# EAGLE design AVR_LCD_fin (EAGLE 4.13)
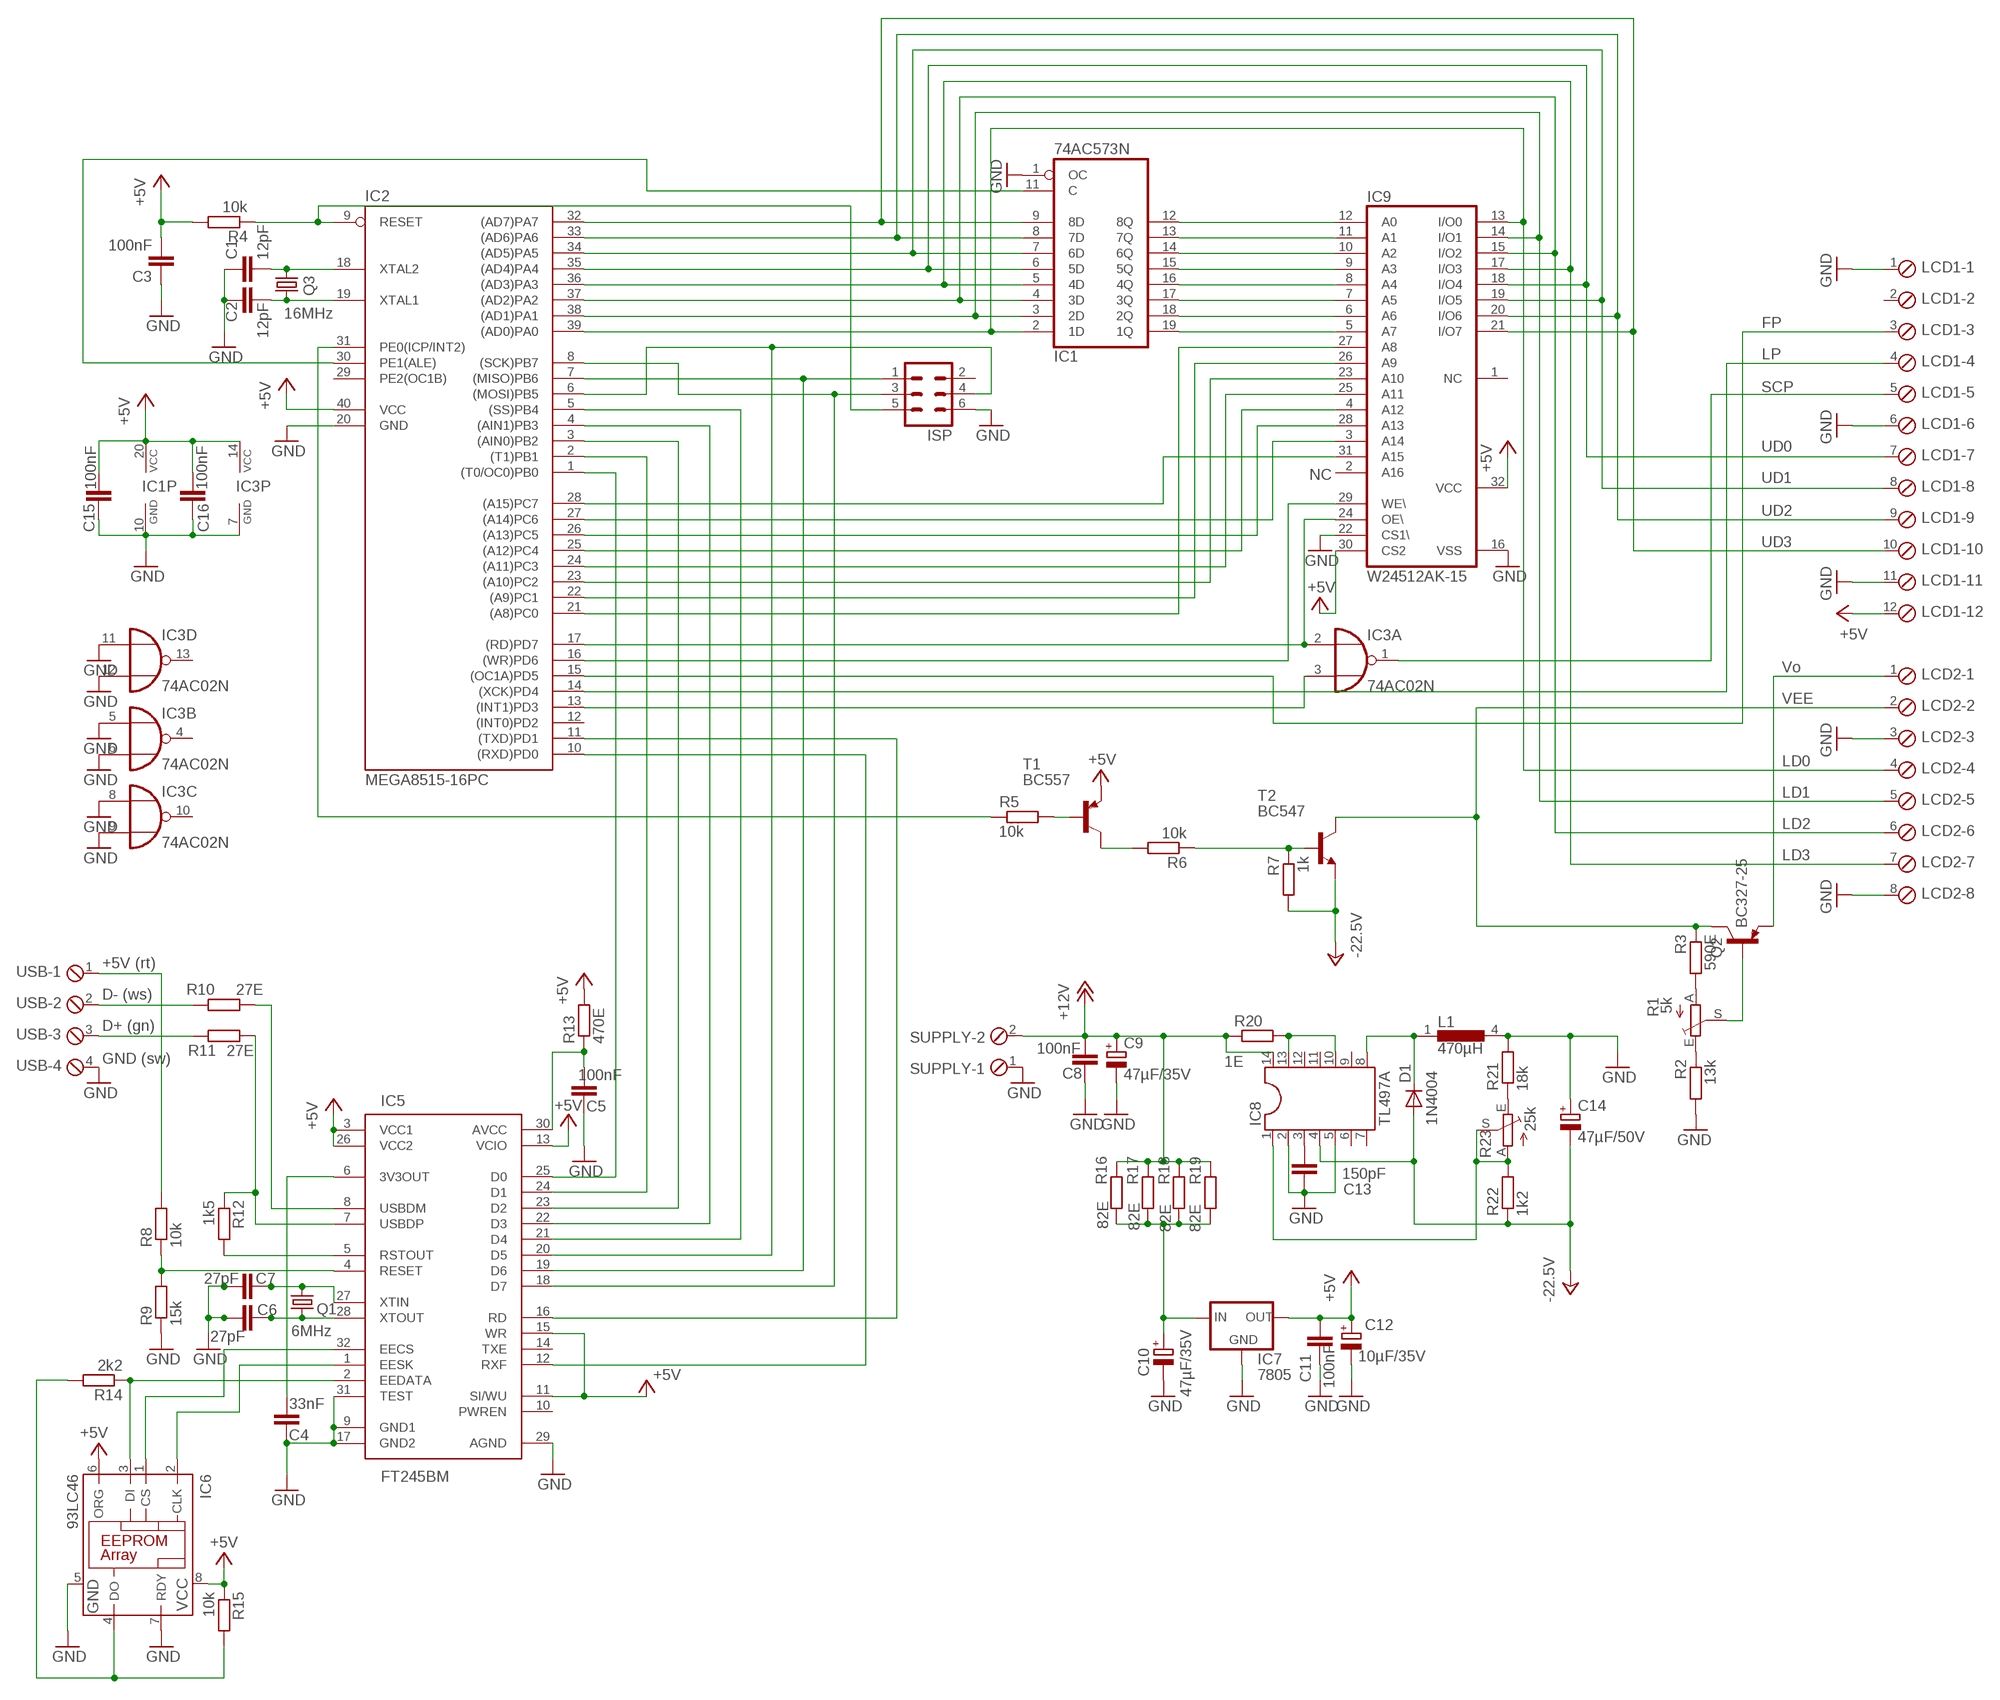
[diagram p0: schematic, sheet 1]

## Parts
C1  12pF  C-EU025-025X050  [C025-025X050]
C2  12pF  C-EU025-025X050  [C025-025X050]
C3  100nF  C-EU025-025X050  [C025-025X050]
C4  33nF  C-EU025-025X050  [C025-025X050]
C5  100nF  C-EU025-025X050  [C025-025X050]
C6  27pF  C-EU025-025X050  [C025-025X050]
C7  27pF  C-EU025-025X050  [C025-025X050]
C8  100nF  C-EU025-025X050  [C025-025X050]
C9  47µF/35V  CPOL-EUE2,5-6E  [E2,5-6E]
C10  47µF/35V  CPOL-EUE2,5-6E  [E2,5-6E]
C11  100nF  C-EU025-025X050  [C025-025X050]
C12  10µF/35V  CPOL-EUE2,5-6E  [E2,5-6E]
C13  150pF  C-EU025-025X050  [C025-025X050]
C14  47µF/50V  CPOL-EUE2,5-6E  [E2,5-6E]
C15  100nF  C-EU025-025X050  [C025-025X050]
C16  100nF  C-EU025-025X050  [C025-025X050]
D1  1N4004  [DO41-10]
IC1  74AC573N  [DIL20]
IC2  MEGA8515-16PC  MEGA8515-P  [DIL40]
IC3  74AC02N  [DIL14]
IC5  FT245BM  [QFP-32]
IC6  93LC46  59C11P  [DIL8]
IC7  7805  78XXL  [78XXL]
IC8  TL497A  DIL14S  [SOCKED-14]
IC9  W24512AK-15  628128PDIL32-3  [DIL32-3]
ISP  ML6  [ML6]
L1  470µH  SPULE  [DSH02]
LCD1  MPT12  [12POL254]
LCD2  MPT8  [8POL254]
Q1  6MHz  CRYTALHC49U70  [HC49U70]
Q2  BC327-25  [TO92-EBC]
Q3  16MHz  CRYTALHC49U-V  [HC49U-V]
R1  5k  TRIM_EU-LI10  [LI10]
R2  13k  R-EU_0207/7  [0207/7]
R3  590E  R-EU_0207/7  [0207/7]
R4  10k  R-EU_0207/7  [0207/7]
R5  10k  R-EU_0207/7  [0207/7]
R6  10k  R-EU_0207/7  [0207/7]
R7  1k  R-EU_0207/7  [0207/7]
R8  10k  R-EU_0207/7  [0207/7]
R9  15k  R-EU_0207/7  [0207/7]
R10  27E  R-EU_0207/7  [0207/7]
R11  27E  R-EU_0207/7  [0207/7]
R12  1k5  R-EU_0207/7  [0207/7]
R13  470E  R-EU_0207/7  [0207/7]
R14  2k2  R-EU_0207/7  [0207/7]
R15  10k  R-EU_0207/7  [0207/7]
R16  82E  R-EU_0207/7  [0207/7]
R17  82E  R-EU_0207/7  [0207/7]
R18  82E  R-EU_0207/7  [0207/7]
R19  82E  R-EU_0207/7  [0207/7]
R20  1E  R-EU_MELF0204W  [MINI_MELF-0204W]
R21  18k  R-EU_0207/7  [0207/7]
R22  1k2  R-EU_0207/7  [0207/7]
R23  25k  TRIM_EU-LI10  [LI10]
SUPPLY  MPT2  [2POL254]
T1  BC557  BC557B-PNP-TO92-EBC  [TO92-EBC]
T2  BC547  BC547B-NPN-TO92-EBC  [TO92-EBC]
USB  MPT4  [4POL254]

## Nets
+5V: C3.2 C11.2 C12.+ C15.2 C16.2 IC1.20(VCC) IC2.40(VCC) IC3.14(P:VCC) IC5.3(VCC1) IC5.11(SI/WU) IC5.13(VCIO) IC5.15(WR) IC5.26(VCC2) IC6.6(ORG) IC6.8(VCC) IC7.OUT IC9.30(CS2) IC9.32(VCC) LCD1.12 R4.2 R13.2 R15.1 T1.E
+12V: C8.2 C9.+ IC8.14 R16.2 R17.2 R18.2 R19.2 R20.1 SUPPLY.2
-24V: C14.- D1.A IC8.4 R7.2 R22.1 T2.E ; supply symbol labelled -22.5V
GND: C1.1 C2.1 C3.1 C4.1 C5.1 C6.2 C7.2 C8.1 C9.- C10.- C11.1 C12.- C13.1 C14.+ C15.1 C16.1 IC1.1(OC) IC1.10(GND) IC2.20(GND) IC3.5(B:I0) IC3.6(B:I1) IC3.7(P:GND) IC3.8(C:I0) IC3.9(C:I1) IC3.11(D:I0) IC3.12(D:I1) IC5.9(GND1) IC5.17(GND2) IC5.29(AGND) IC5.31(TEST) IC6.5(GND) IC6.7(RDY) IC7.GND IC8.2 IC8.5 IC9.16(VSS) IC9.22(CS1\) ISP.6 L1.4 LCD1.1 LCD1.6 LCD1.11 LCD2.3 LCD2.8 R2.2 R9.1 R21.2 SUPPLY.1 USB.4
N$1: R1.E R2.1
N$2: R1.A R3.2
N$3: IC2.9(RESET) ISP.5 R4.1
N$4: C1.2 IC2.18(XTAL2) Q3.2
N$5: C2.2 IC2.19(XTAL1) Q3.1
N$6: Q2.B R1.S
N$7: LCD2.1 Q2.E
N$8: R6.2 T1.C
N$9: R6.1 R7.1 T2.B
N$10: LCD2.2 Q2.C R3.1 T2.C
N$11: IC2.31(PE0(ICP/INT2)) R5.1
N$12: R5.2 T1.B
N$13: IC1.9(8D) IC2.32((AD7)PA7) IC9.21(I/O7) LCD1.10
N$14: IC1.8(7D) IC2.33((AD6)PA6) IC9.20(I/O6) LCD1.9
N$15: IC1.7(6D) IC2.34((AD5)PA5) IC9.19(I/O5) LCD1.8
N$16: IC1.6(5D) IC2.35((AD4)PA4) IC9.18(I/O4) LCD1.7
N$17: IC1.5(4D) IC2.36((AD3)PA3) IC9.17(I/O3) LCD2.7
N$18: IC1.4(3D) IC2.37((AD2)PA2) IC9.15(I/O2) LCD2.6
N$19: IC2.7((MISO)PB6) IC5.19(D6) ISP.1
N$20: IC2.8((SCK)PB7) IC5.18(D7) ISP.3
N$21: IC2.6((MOSI)PB5) IC5.20(D5) ISP.4
N$22: IC1.3(2D) IC2.38((AD1)PA1) IC9.14(I/O1) LCD2.5
N$23: IC1.2(1D) IC2.39((AD0)PA0) IC9.13(I/O0) LCD2.4
N$24: IC1.12(8Q) IC9.12(A0)
N$25: IC1.13(7Q) IC9.11(A1)
N$26: IC1.14(6Q) IC9.10(A2)
N$27: IC1.15(5Q) IC9.9(A3)
N$28: IC1.16(4Q) IC9.8(A4)
N$29: IC1.17(3Q) IC9.7(A5)
N$30: IC1.18(2Q) IC9.6(A6)
N$31: IC1.19(1Q) IC9.5(A7)
N$32: IC2.17((RD)PD7) IC3.2(A:I0) IC9.24(OE\)
N$33: IC2.16((WR)PD6) IC9.29(WE\)
N$34: IC2.13((INT1)PD3) IC3.3(A:I1)
N$35: IC3.1(A:O) LCD1.5
N$36: IC2.15((OC1A)PD5) LCD1.3
N$37: IC2.14((XCK)PD4) LCD1.4
N$38: IC1.11(C) IC2.30(PE1(ALE))
N$39: IC2.21((A8)PC0) IC9.27(A8)
N$40: IC2.22((A9)PC1) IC9.26(A9)
N$41: IC2.23((A10)PC2) IC9.23(A10)
N$42: IC2.24((A11)PC3) IC9.25(A11)
N$43: IC2.25((A12)PC4) IC9.4(A12)
N$44: IC2.26((A13)PC5) IC9.28(A13)
N$45: IC2.27((A14)PC6) IC9.3(A14)
N$46: IC2.1((T0/OC0)PB0) IC5.25(D0)
N$47: IC2.2((T1)PB1) IC5.24(D1)
N$48: IC2.3((AIN0)PB2) IC5.23(D2)
N$49: IC2.4((AIN1)PB3) IC5.22(D3)
N$50: IC2.5((SS)PB4) IC5.21(D4)
N$51: IC2.10((RXD)PD0) IC5.12(RXF)
N$53: IC5.4(RESET) R8.1 R9.2
N$54: R8.2 USB.1
N$55: R10.2 USB.2
N$56: R11.2 USB.3
N$57: IC5.7(USBDP) R11.1 R12.1
N$58: IC5.8(USBDM) R10.1
N$59: IC5.5(RSTOUT) R12.2
N$60: C4.2 IC5.6(3V3OUT)
N$61: C5.2 IC5.30(AVCC) R13.1
N$62: IC5.2(EEDATA) IC6.3(DI) R14.1
N$63: IC6.4(DO) R14.2 R15.2
N$64: IC5.32(EECS) IC6.1(CS)
N$65: IC5.1(EESK) IC6.2(CLK)
N$67: C6.1 IC5.28(XTOUT) Q1.1
N$68: C7.1 IC5.27(XTIN) Q1.2
N$69: C10.+ IC7.IN R16.1 R17.1 R18.1 R19.1
N$70: IC2.28((A15)PC7) IC9.31(A15)
N$71: IC8.10 IC8.13 R20.2
N$73: C13.2 IC8.3
N$75: D1.C IC8.8 L1.1
N$78: R21.1 R23.E
N$79: IC8.1 R22.2 R23.A R23.S
POWERJACK: IC2.11((TXD)PD1) IC5.16(RD)
Unconnected: IC2.12((INT0)PD2) IC2.29(PE2(OC1B)) IC3.4(B:O) IC3.10(C:O) IC3.13(D:O) IC5.10(PWREN) IC5.14(TXE) IC8.6 IC8.7 IC8.9 IC8.11 IC8.12 IC9.1(NC) IC9.2(A16) ISP.2 LCD1.2

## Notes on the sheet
- FP
- LP
- SCP
- UD0
- NC | UD1
- UD2
- UD3
- Vo
- VEE
- LD0
- LD1
- LD2
- LD3
- +5V (rt)
- D- (ws)
- D+ (gn)
- GND (sw)

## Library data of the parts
C1-C8 C11 C13 C15 C16 = rcl:C-EU: CAPACITOR, European symbol
C9 C10 C12 C14 = rcl:CPOL-EU: POLARIZED CAPACITOR, European symbol
D1 = diode:1N4004: DIODE
IC1 = 74xx-eu:74*573: 8-bit D latch BUS DRIVER
IC2 = avr:MEGA8515-P: MICROCONTROLLER 8 Kbytes FLASH 512 bytes SRAM 512 bytes EEPROM USART 8-channel 10 bit ADC
IC3 = 74xx-eu:74*02: Quad 2-input NOR gate
IC5 = FTDI:FT245BM: FT245BM USB-Fifo FTDI
IC6 = microchip:59C11: Serial EEPROM 1 K, 5.0 V, CMOS
IC7 = v-reg:78XXL: VOLTAGE REGULATOR
IC8 = ic-package:DIL14: Dual In Line
IC9 = memory-hitachi:628128P: MEMORY
ISP = con-harting-ml:ML6: HARTING
L1 = inductors:SPULE
LCD1 = con-phoenix-254:MPT12: PHOENIX CONNECTOR
LCD2 = con-phoenix-254:MPT8: PHOENIX CONNECTOR
Q1 Q3 = crystal:CRYTAL: CRYSTAL
Q2 = transistor-pnp:BC327*: PNP Transistror
R1 R23 = pot:TRIM_EU-: POTENTIOMETER
R2-R22 = rcl:R-EU_: RESISTOR, European symbol
SUPPLY = con-phoenix-254:MPT2: PHOENIX CONNECTOR
T1 = transistor:*-PNP-: PNP Transistror
T2 = transistor:*-NPN-: NPN Transistror
USB = con-phoenix-254:MPT4: PHOENIX CONNECTOR

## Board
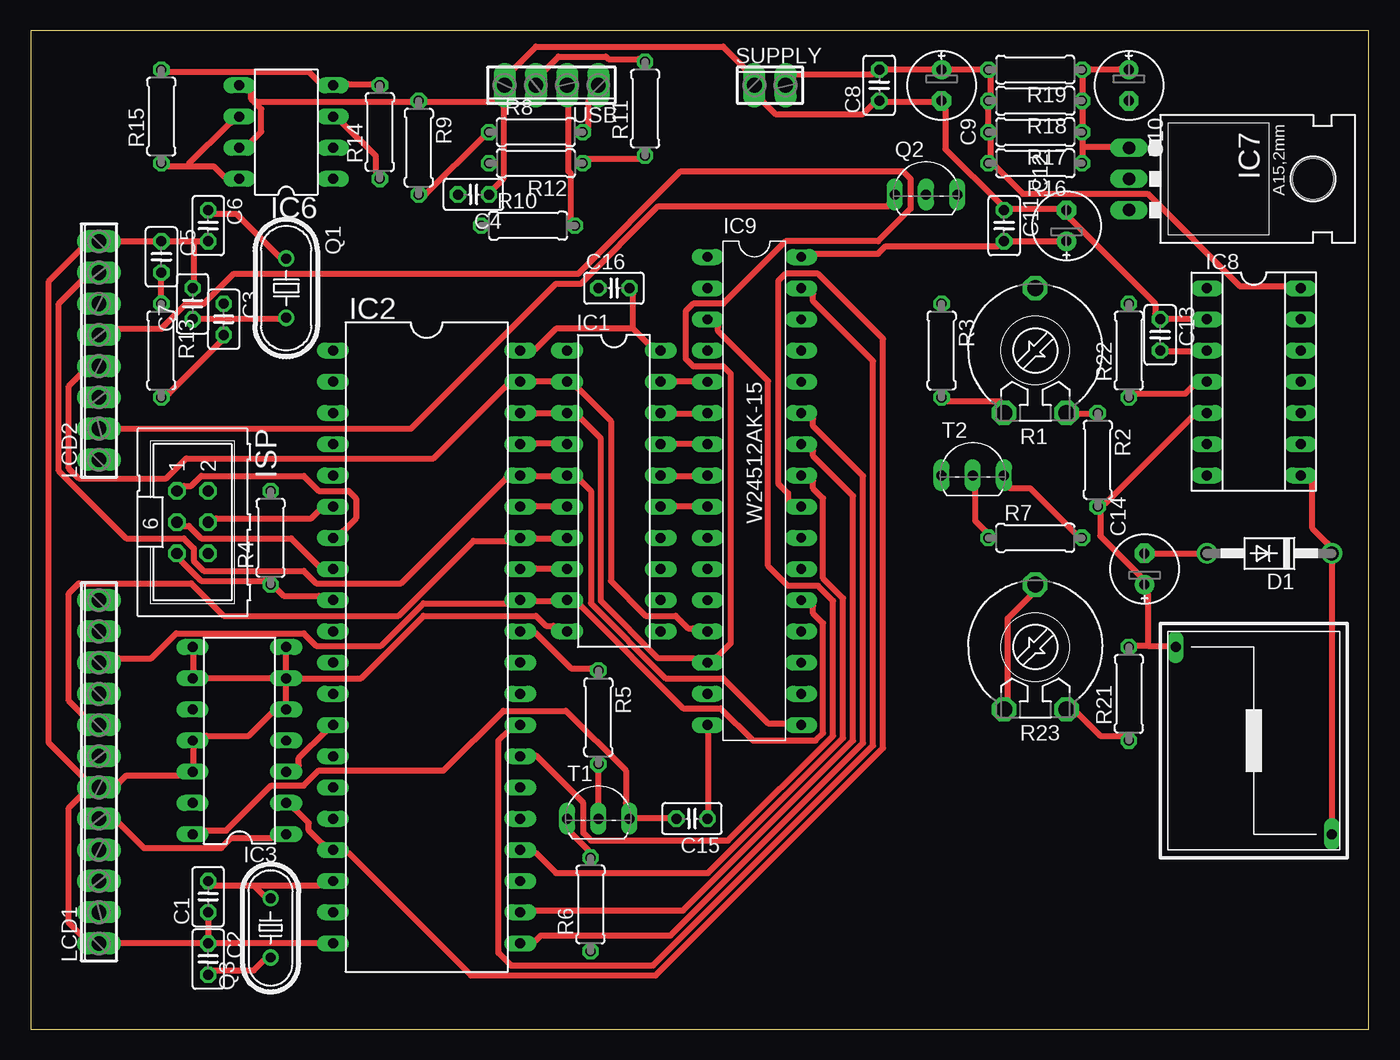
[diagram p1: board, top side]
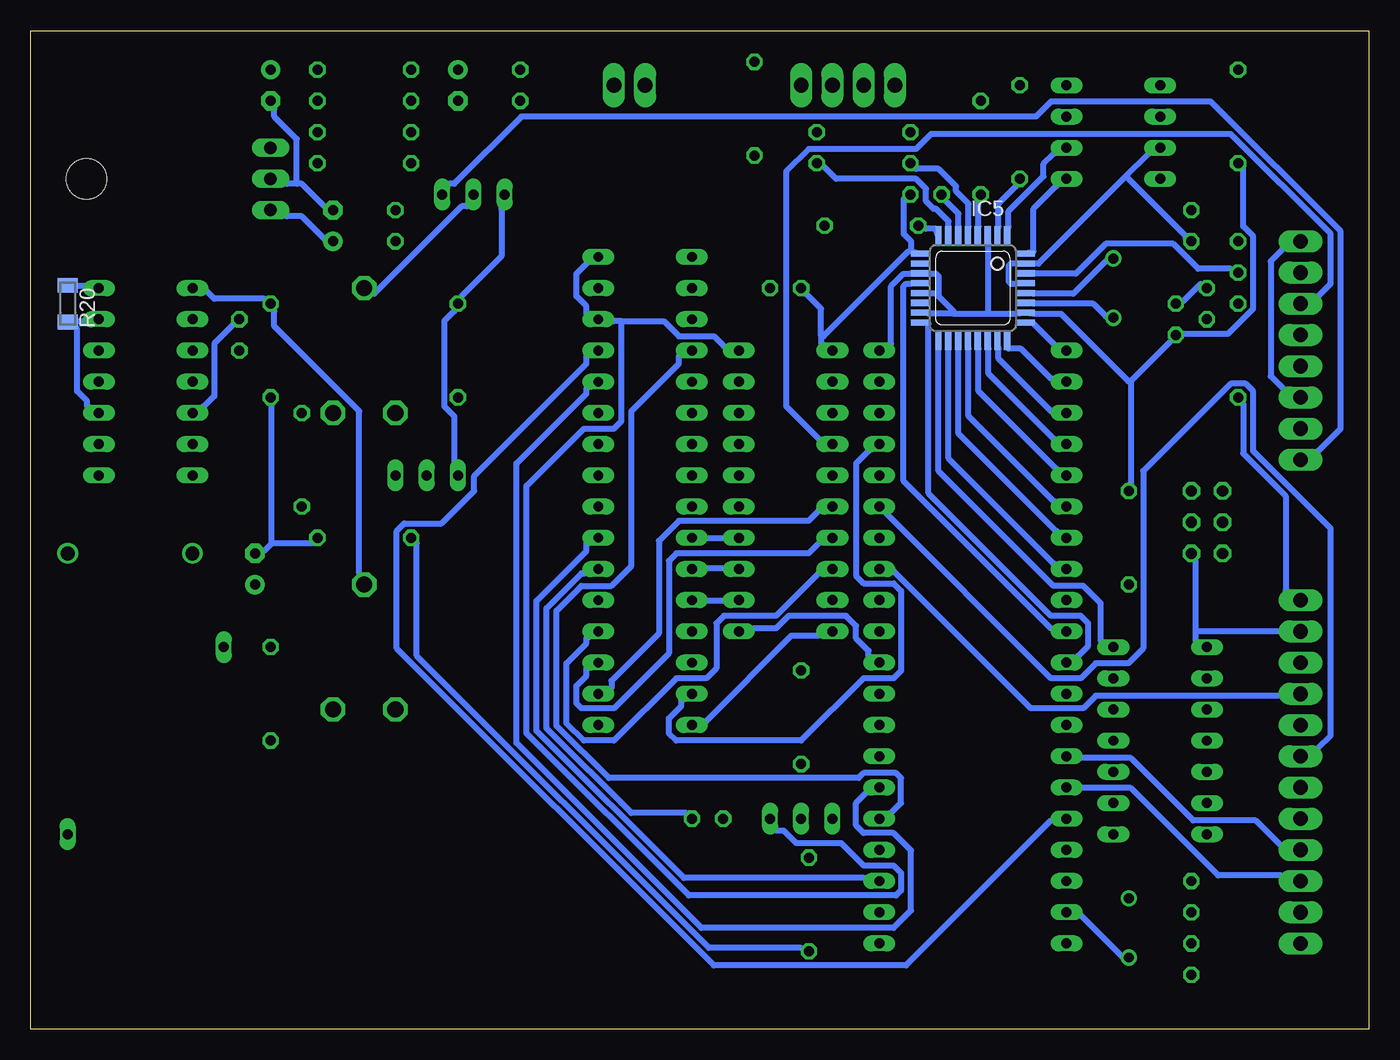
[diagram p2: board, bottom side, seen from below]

Size 108.89 x 81.27 mm. Coordinates in mm from the lower left corner, seen from the top.
Outline: 0,0 108.89,0 108.89,81.27 0,81.27 0,0
Copper layers (1*16): Top 0.035mm / dielectric 1.5mm / Bottom 0.035mm
Design rules "default": minimum track width 20mil, minimum drill 24mil, track to track 8mil, track to pad 8mil, pad to pad 8mil, via to via 8mil, smd to smd 8mil, copper to edge 40mil, drill to drill 8mil, minimum pad ring 10mil, minimum via ring 8mil, stop-mask expansion 4mil, vias tented up to drill 0mil, thermal gap 10mil

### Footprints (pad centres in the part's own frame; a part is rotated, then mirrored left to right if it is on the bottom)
C025-025X050 = drill 0.813 octagon: 1 -1.27,0; 2 1.27,0
E2,5-6E = drill 0.813 pad 1.575 round: + -1.27,0 | drill 0.813 pad 1.575 octagon: - 1.27,0
DO41-10 = drill 1.118 round: A 5.08,0; C -5.08,0
DIL20 = drill 0.813 long: 1 -11.43,-3.81; 2 -8.89,-3.81; 3 -6.35,-3.81; 4 -3.81,-3.81; 5 -1.27,-3.81; 6 1.27,-3.81; 7 3.81,-3.81; 8 6.35,-3.81; 9 8.89,-3.81; 10 11.43,-3.81; 11 11.43,3.81; 12 8.89,3.81; 13 6.35,3.81; 14 3.81,3.81; 15 1.27,3.81; 16 -1.27,3.81; 17 -3.81,3.81; 18 -6.35,3.81; 19 -8.89,3.81; 20 -11.43,3.81
DIL40 = drill 0.813 long: 1 -24.13,-7.62; 2 -21.59,-7.62; 3 -19.05,-7.62; 4 -16.51,-7.62; 5 -13.97,-7.62; 6 -11.43,-7.62; 7 -8.89,-7.62; 8 -6.35,-7.62; 9 -3.81,-7.62; 10 -1.27,-7.62; 11 1.27,-7.62; 12 3.81,-7.62; 13 6.35,-7.62; 14 8.89,-7.62; 15 11.43,-7.62; 16 13.97,-7.62; 17 16.51,-7.62; 18 19.05,-7.62; 19 21.59,-7.62; 20 24.13,-7.62; 21 24.13,7.62; 22 21.59,7.62; 23 19.05,7.62; 24 16.51,7.62; 25 13.97,7.62; 26 11.43,7.62; 27 8.89,7.62; 28 6.35,7.62; 29 3.81,7.62; 30 1.27,7.62; 31 -1.27,7.62; 32 -3.81,7.62; 33 -6.35,7.62; 34 -8.89,7.62; 35 -11.43,7.62; 36 -13.97,7.62; 37 -16.51,7.62; 38 -19.05,7.62; 39 -21.59,7.62; 40 -24.13,7.62
DIL14 = drill 0.813 long: 1 -7.62,-3.81; 2 -5.08,-3.81; 3 -2.54,-3.81; 4 0,-3.81; 5 2.54,-3.81; 6 5.08,-3.81; 7 7.62,-3.81; 8 7.62,3.81; 9 5.08,3.81; 10 2.54,3.81; 11 0,3.81; 12 -2.54,3.81; 13 -5.08,3.81; 14 -7.62,3.81
QFP-32 = smd 0.508 x 1.6: 1 -2.8,-4.25; 2 -2,-4.25; 3 -1.2,-4.25; 4 -0.4,-4.25; 5 0.4,-4.25; 6 1.2,-4.25; 7 2,-4.25; 8 2.8,-4.25; 17 2.8,4.25; 18 2,4.25; 19 1.2,4.25; 20 0.4,4.25; 21 -0.4,4.25; 22 -1.2,4.25; 23 -2,4.25; 24 -2.8,4.25 | smd 1.6 x 0.508: 9 4.25,-2.8; 10 4.25,-2; 11 4.25,-1.2; 12 4.25,-0.4; 13 4.25,0.4; 14 4.25,1.2; 15 4.25,2; 16 4.25,2.8; 25 -4.25,2.8; 26 -4.25,2; 27 -4.25,1.2; 28 -4.25,0.4; 29 -4.25,-0.4; 30 -4.25,-1.2; 31 -4.25,-2; 32 -4.25,-2.8
DIL8 = drill 0.813 long: 1 -3.81,-3.81; 2 -1.27,-3.81; 3 1.27,-3.81; 4 3.81,-3.81; 5 3.81,3.81; 6 1.27,3.81; 7 -1.27,3.81; 8 -3.81,3.81
78XXL = drill 1.016 long: GND 0,-3.81; IN -2.54,-3.81; OUT 2.54,-3.81 | hole 3.302: 0,11.176
SOCKED-14 = drill 0.813 long: 1 -7.62,-3.81; 2 -5.08,-3.81; 3 -2.54,-3.81; 4 0,-3.81; 5 2.54,-3.81; 6 5.08,-3.81; 7 7.62,-3.81; 8 7.62,3.81; 9 5.08,3.81; 10 2.54,3.81; 11 0,3.81; 12 -2.54,3.81; 13 -5.08,3.81; 14 -7.62,3.81
DIL32-3 = drill 0.8 long: 1 -17.78,-3.81; 2 -15.24,-3.81; 3 -12.7,-3.81; 4 -10.16,-3.81; 5 -7.62,-3.81; 6 -5.08,-3.81; 7 -2.54,-3.81; 8 0,-3.81; 9 2.54,-3.81; 10 5.08,-3.81; 11 7.62,-3.81; 12 10.16,-3.81; 13 12.7,-3.81; 14 15.24,-3.81; 15 17.78,-3.81; 16 20.32,-3.81; 17 20.32,3.81; 18 17.78,3.81; 19 15.24,3.81; 20 12.7,3.81; 21 10.16,3.81; 22 7.62,3.81; 23 5.08,3.81; 24 2.54,3.81; 25 0,3.81; 26 -2.54,3.81; 27 -5.08,3.81; 28 -7.62,3.81; 29 -10.16,3.81; 30 -12.7,3.81; 31 -15.24,3.81; 32 -17.78,3.81
ML6 = drill 0.914 octagon: 1 -2.54,-1.27; 2 -2.54,1.27; 3 0,-1.27; 4 0,1.27; 5 2.54,-1.27; 6 2.54,1.27
DSH02 = drill 0.8 long: 1 -8.89,-1.27; 4 6.35,11.43
12POL254 = drill 1.2 long: 1 -13.97,0; 2 -11.43,0; 3 -8.89,0; 4 -6.35,0; 5 -3.81,0; 6 -1.27,0; 7 1.27,0; 8 3.81,0; 9 6.35,0; 10 8.89,0; 11 11.43,0; 12 13.97,0
8POL254 = drill 1.2 long: 1 -8.89,0; 2 -6.35,0; 3 -3.81,0; 4 -1.27,0; 5 1.27,0; 6 3.81,0; 7 6.35,0; 8 8.89,0
HC49U70 = drill 0.813 round: 1 -2.413,0; 2 2.413,0
TO92-EBC = drill 0.813 long: B 0,-1.27; C -2.54,-1.27; E 2.54,-1.27
HC49U-V = drill 0.813 round: 1 -2.413,0; 2 2.413,0
LI10 = drill 1.321 octagon: A -2.54,-5.08; E 2.54,-5.08; S 0,5.08
0207/7 = drill 0.813 octagon: 1 -3.81,0; 2 3.81,0
MINI_MELF-0204W = smd 1.2 x 1.6: 1 -1.5,0; 2 1.5,0
2POL254 = drill 1.2 long: 1 -1.27,0; 2 1.27,0
4POL254 = drill 1.2 long: 1 -3.81,0; 2 -1.27,0; 3 1.27,0; 4 3.81,0

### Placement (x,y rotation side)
C1  14.44,10.79 90 top
C2  14.44,5.71 270 top
C3  15.71,57.78 270 top
C4  36.03,67.94 180 top
C5  10.63,62.86 270 top
C6  14.44,65.4 270 top
C7  13.17,59.05 90 top
C8  69.05,76.83 90 top
C9  74.13,76.83 270 top
C10  89.37,76.83 270 top
C11  79.21,65.4 270 top
C12  84.29,65.4 90 top
C13  91.91,56.51 270 top
C14  90.64,37.46 90 top
C15  53.81,17.14 180 top
C16  47.46,60.32 0 top
D1  100.8,38.73 180 top
IC1  47.46,43.81 270 top
IC2  32.22,31.11 270 top
IC3  16.98,23.49 90 top
IC5  32.22,60.32 180 bottom
IC6  20.79,73.02 90 top
IC7  93.18,69.21 270 top
IC8  99.53,52.7 270 top
IC9  58.89,45.08 270 top
ISP  13.17,41.27 270 top
L1  104.61,24.76 90 top
LCD1  5.55,20.95 90 top
LCD2  5.55,55.24 90 top
Q1  20.79,60.32 270 top
Q2  72.86,69.21 0 top
Q3  19.52,8.25 90 top
R1  81.75,55.24 0 top
R2  86.83,46.35 270 top
R3  74.13,55.24 270 top
R4  19.52,40 90 top
R5  46.19,25.39 270 top
R6  45.55,10.15 90 top
R7  81.75,40 0 top
R8  41.11,73.02 0 top
R9  31.59,71.75 270 top
R10  40.47,65.4 0 top
R11  50,74.92 90 top
R12  41.11,70.48 180 top
R13  10.63,55.24 270 top
R14  28.41,73.02 90 top
R15  10.63,74.29 90 top
R16  81.75,70.48 180 top
R17  81.75,73.02 180 top
R18  81.75,75.56 180 top
R19  81.75,78.1 180 top
R20  105.88,59.05 270 bottom
R21  89.37,27.3 90 top
R22  89.37,55.24 90 top
R23  81.75,31.11 0 top
SUPPLY  60.16,76.83 0 top
T1  46.19,18.41 0 top
T2  76.67,46.35 0 top
USB  42.38,76.83 180 top

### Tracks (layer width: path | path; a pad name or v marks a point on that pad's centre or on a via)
+5V
  Top 0.508: 12.87,70.23 14.9,70.23 15.71,69.41 IC6.8 | 12.87,70.23 11.24,70.23 R15.1 | IC6.6 16.12,73.68 12.87,70.43 12.87,70.23 | R13.2 11.24,51.74 15.51,56 C3.2 | IC3.14 14.29,16.18 15.91,16.18 19.57,19.83 22.21,19.83 23.43,21.05 33.59,21.05 38.47,25.93 43.55,25.93 48.42,21.05 48.42,18.41 T1.E 49.24,17.19 52.08,17.19 C15.2 | C12.+ C11.2 78.7,63.72 69.56,63.72 68.95,63.11 63.87,63.11 IC9.32 | 49.03,57.02 49.03,59.86 C16.2 | 49.03,57.02 50.25,55.8 IC1.20 | IC2.40 41.11,55.39 42.74,57.02 49.03,57.02
  Bottom 0.508: 19.37,52.75 19.37,44.42 R4.2 | 19.37,52.75 16.12,56 C3.2 15.1,56.61 11.44,56.61 9.41,58.64 9.41,64.54 10.22,65.35 10.22,70.02 R15.1 | LCD1.12 6.77,35.68 6.77,43.4 10.22,46.86 10.22,50.92 R13.2 | 33.8,58.24 35.83,58.24 IC5.15 | 33.8,58.24 30.95,58.24 | 30.95,58.24 28.71,58.24 IC5.26 27.29,58.24 25.06,58.24 19.57,52.75 19.37,52.75 | 35.22,59.86 35.83,59.86 IC5.13 | 35.22,59.86 33.8,58.44 33.8,58.24 | 35.22,59.86 35.01,59.86 35.01,61.29 35.22,61.49 35.83,61.49 IC5.11 37.25,61.49 37.86,61.49 38.88,60.47 38.88,55.8 IC2.40 | IC5.3 30.95,63.93 30.95,58.24 | IC7.OUT 88.05,66.16 86.83,66.16 85,64.33 C12.+ | IC9.32 63.66,62.3 64.48,61.49 64.48,59.66 63.66,58.85 63.66,58.24 IC9.30 61.43,57.63 60.82,57.63 | 60.82,57.63 57.37,57.63 56.15,56.41 53.3,56.41 52.49,55.6 IC1.20 | T1.E 48.22,16.18 47.61,16.18 46.6,15.16 42.94,15.16 41.11,13.33 38.67,13.33 38.06,12.72 38.06,11.3 38.47,10.89 55.33,10.89 68.54,24.1 68.54,44.22 63.87,48.89 61.43,48.89 60.82,49.5 60.82,57.63
+12V
  Top 0.508: SUPPLY.2 62.24,77.74 68.54,77.74 C8.2 69.56,78.15 73.42,78.15 C9.+ 74.84,78.15 77.48,78.15 R19.2 78.09,77.54 78.09,76.12 R18.2 77.89,75.1 77.89,73.48 R17.2 78.09,72.46 78.09,71.04 R16.2 78.5,70.23 80.73,67.99 90.89,67.99 98.41,60.47 102.07,60.47 IC8.14
  Bottom 0.508: R20.1 105.12,60.47 104.51,60.47 IC8.14
-24V
  Top 0.508: R22.1 89.88,51.74 93.94,51.74 94.55,52.34 IC8.4 | T2.E 79.72,44.01 81.34,44.01 85,40.36 R7.2 | C14.- D1.A
  Bottom 0.508: 89.27,39.54 86.02,39.54 R7.2 | 89.27,39.54 89.88,38.93 C14.- | R22.1 89.27,50.92 89.27,39.54
GND
  Top 0.508: IC9.16 55.13,24.3 55.13,17.6 C15.1 | C2.1 14.49,7.44 14.49,9.06 C1.1 | IC2.20 23.43,7.03 14.9,7.03 C2.1 | C2.1 13.88,7.03 7.18,7.03 LCD1.1 4.13,7.64 3.11,8.66 3.11,18 4.13,19.02 LCD1.6 | IC3.8 13.27,30.6 13.27,29.18 IC3.9 IC3.6 | LCD1.6 7.18,20.04 7.79,20.64 12.05,20.64 IC3.12 13.27,21.46 13.27,22.88 IC3.11 14.29,23.9 17.74,23.9 19.57,25.73 IC3.5 IC3.6 | IC3.6 IC3.7 | IC1.10 42.53,32.84 41.92,32.84 41.11,33.65 31.97,33.65 26.89,28.57 IC3.6 | USB.4 37.86,75.51 32.17,75.51 R9.1 30.95,75.51 18.35,75.51 18.25,75.41 | USB.4 38.47,75.1 38.47,69.21 37.66,68.4 C4.1 | 13.27,64.13 C5.1 LCD2.8 4.13,63.52 1.49,60.88 1.49,23.29 4.33,20.44 LCD1.6 | 18.25,75.41 18.76,74.9 18.76,73.07 17.95,72.26 IC6.7 | 18.25,75.41 17.95,75.71 17.95,76.32 IC6.5 | IC8.2 94.55,57.83 92.52,57.83 C13.1 91.5,58.24 91.5,59.05 84.59,65.96 C12.- 83.58,66.77 79.72,66.77 C11.1 78.91,67.18 74.44,71.65 74.44,74.9 C9.- 73.42,75.51 69.56,75.51 C8.1 68.54,75.31 67.73,74.49 60.62,74.49 59.6,75.51 SUPPLY.1 58.18,78.15 56.35,79.98 41.11,79.98 39.28,78.15 USB.4 | 90.89,31.21 89.88,31.21 R21.2 | 90.89,31.21 92.72,31.21 L1.4 | IC8.5 94.55,49.91 87.44,42.79 R2.2 87.03,41.98 87.03,40.15 90.28,36.9 C14.+ 90.89,35.48 90.89,31.21 | C7.2 13.27,60.68 13.27,64.13 | 13.27,64.13 C6.2
  Bottom 0.508: IC9.22 63.87,37.1 64.07,37.1 66.92,34.26 66.92,24.51 60.01,17.6 55.54,17.6 C15.1 | IC1.10 44.77,32.02 47,32.02 53.91,25.12 IC9.16 | 14.08,32.43 14.08,31.62 IC3.8 | 14.08,32.43 14.08,38.12 ISP.6 | LCD1.11 7.18,32.43 14.08,32.43 | IC5.17 35.01,55.39 35.01,45.44 25.67,36.09 23.23,36.09 21.81,34.67 21.81,31.62 IC3.7 | 37.25,63.32 37.25,64.13 37.86,64.74 37.86,67.58 C4.1 | 37.25,63.32 IC5.9 | 44.56,56.41 44.56,58.64 45.78,59.86 C16.1 | 44.56,56.41 44.56,55.8 IC1.1 | 37.25,63.32 37.45,63.32 44.36,56.41 44.56,56.41 | 13.78,60.57 15.1,59.25 C3.1 | 13.78,60.57 13.68,60.68 | LCD2.3 6.97,52.14 7.99,53.16 7.99,62.5 6.97,63.52 LCD2.8 | IC5.29 28.71,60.68 29.12,60.68 29.32,60.88 29.32,62.1 29.12,62.3 28.71,62.3 IC5.31 27.29,62.3 26.89,62.3 19.77,69.41 | 19.77,69.41 17.95,71.24 IC6.7 | 19.77,69.41 14.9,64.54 14.9,64.33 C6.2 | C13.1 92.32,57.42 93.94,55.8 93.94,51.53 94.75,50.72 IC8.5 | 87.24,68.8 86.83,68.8 85,66.98 C12.- | 87.24,68.8 88.05,68.8 IC7.GND | C10.- 89.06,74.9 89.06,74.29 87.24,72.46 87.24,68.8 | C7.2 13.68,60.47 13.78,60.57
N$1
  Top 0.508: R2.1 86.22,50.11 85.2,50.11 R1.E
N$2
  Top 0.508: R3.2 74.64,51.12 78.91,51.12 R1.A
N$3
  Top 0.508: IC2.9 23.43,35.28 20.59,35.28 19.98,35.89 R4.1 18.96,36.5 13.88,36.5 12.26,38.12 ISP.5
N$4
  Top 0.508: 18.15,11.7 14.9,11.7 C1.2 | 18.15,11.7 18.96,10.89 Q3.2 | IC2.18 23.43,11.7 18.15,11.7
N$5
  Top 0.508: C2.2 14.9,4.8 18.15,4.8 18.96,5.61 Q3.1
  Bottom 0.508: IC2.19 23.43,9.27 19.98,5.81 Q3.1
N$6
  Bottom 0.508: Q2.B 73.42,66.98 73.83,66.98 80.94,59.86 R1.S
N$7
  Bottom 0.508: Q2.E 74.84,68.8 74.44,68.8 68.95,74.29 27.09,74.29 25.87,75.51 12.87,75.51 2.3,64.94 2.3,48.89 4.13,47.06 LCD2.1
N$8
  Top 0.508: R6.2 45.38,14.55 43.95,15.97 T1.C
N$9
  Top 0.508: T2.B 76.87,43.81 76.87,41.37 77.69,40.56 R7.1
  Bottom 0.508: R6.1 46.19,6.62 53.71,6.62 77.48,30.4 77.48,39.54 R7.1
N$10
  Top 0.508: LCD2.2 30.95,48.89 42.74,60.68 44.77,60.68 51.07,66.98 69.76,66.98 Q2.C
  Bottom 0.508: T2.C 74.44,46.25 74.44,49.91 75.25,50.72 75.25,57.63 74.44,58.44 R3.1 73.83,59.66 70.57,62.91 70.57,66.77 Q2.C
N$11
  Top 0.508: IC2.31 41.11,32.23 43.95,29.38 45.58,29.38 R5.1
N$12
  Top 0.508: T1.B R5.2
N$13
  Top 0.508: IC9.21 63.66,34.46 63.66,33.85 64.48,33.04 64.48,24.1 63.87,23.49 58.79,23.49 56.15,26.13 53.1,26.13 44.77,34.46 IC1.9 42.53,34.87 41.11,34.87 IC2.32 38.67,34.67 31.97,34.67 28.51,31.21 23.23,31.21 22.21,32.23 11.85,32.23 9.82,30.2 7.18,30.2 LCD1.10
N$14
  Top 0.508: IC2.33 41.11,37.51 42.53,37.51 IC1.8
  Bottom 0.508: IC9.20 63.66,31.82 63.66,31.42 65.29,29.79 65.29,24.91 63.87,23.49 61.43,23.49 56.35,28.57 53.91,28.57 53.1,29.38 53.1,33.04 52.49,33.65 48.22,33.65 44.77,37.1 IC1.8 | LCD1.9 7.18,27.15 22.21,27.15 23.23,26.13 27.5,26.13 38.67,37.31 IC2.33
N$15
  Top 0.508: IC1.7 42.53,39.95 41.11,39.95 IC2.34 38.67,39.75 36.03,39.75 29.93,33.65 15.71,33.65 13.07,36.29 3.92,36.29 3.11,35.48 3.11,26.74 4.33,25.52 LCD1.8
  Bottom 0.508: IC9.19 63.66,29.38 63.66,28.77 64.48,27.96 64.48,26.54 64.07,26.13 61.43,26.13 56.96,30.6 56.96,38.12 56.35,38.73 45.58,38.73 44.77,39.54 IC1.7
N$16
  Top 0.508: IC2.35 41.11,42.59 42.53,42.59 IC1.6
  Bottom 0.508: IC9.18 61.63,27.76 61.63,28.37 57.77,32.23 57.77,39.75 56.15,41.37 45.58,41.37 44.77,42.18 IC1.6 | LCD1.7 4.13,22.88 3.11,23.9 3.11,40.76 9.41,47.06 9.41,51.94 10.02,52.55 11.24,52.55 18.35,45.44 18.35,31.01 19.57,29.79 22.21,29.79 23.43,28.57 25.87,28.57 IC2.35
N$17
  Top 0.508: IC9.17 61.43,24.91 60.01,24.91 56.35,28.57 51.68,28.57 45.58,34.67 45.58,43.81 44.77,44.62 IC1.5 42.53,45.03 41.11,45.03 IC2.36 38.67,44.83 30.14,36.29 23.23,36.29 22.21,37.31 14.08,37.31 13.27,38.12 13.27,39.14 12.46,39.95 7.79,39.95 2.3,45.44 2.3,59.05 4.13,60.88 LCD2.7
N$18
  Top 0.508: IC1.4 42.53,47.67 41.11,47.67 IC2.37
  Bottom 0.508: IC9.15 55.94,26.74 55.94,26.34 56.96,25.32 56.96,24.1 56.35,23.49 46.19,23.49 41.11,28.57 38.67,28.57 38.06,29.18 38.06,35.68 38.67,36.29 41.11,36.29 41.72,36.9 41.72,46.05 40.7,47.06 IC2.37 | LCD2.6 4.13,59.66 3.11,60.68 3.11,64.74 11.24,72.87 35.62,72.87 36.84,71.65 45.58,71.65 47.41,69.82 47.41,50.72 44.77,48.08 IC1.4
N$19
  Top 0.508: ISP.1 12.46,44.22 13.07,44.22 13.88,45.03 22.21,45.03 23.43,43.81 25.87,43.81 26.48,43.2 26.48,41.58 25.46,40.56 IC2.7
  Bottom 0.508: IC5.19 33.39,55.39 33.39,48.48 25.46,40.56 IC2.7
N$20
  Top 0.508: ISP.3 12.46,40.97 12.87,40.97 13.88,39.95 21.2,39.95 23.43,37.71 IC2.8
  Bottom 0.508: IC5.18 34.2,55.39 34.2,46.45 25.67,37.92 IC2.8
N$21
  Top 0.508: ISP.4 15.1,41.58 22.82,41.58 23.43,42.18 IC2.6
  Bottom 0.508: IC5.20 32.58,55.39 32.58,49.91 25.67,43 IC2.6
N$22
  Top 0.508: IC2.38 41.11,50.11 42.53,50.11 IC1.3 44.77,49.7 46.39,48.08 46.39,34.87 51.07,30.2 53.91,30.2 IC9.14 55.94,30.4 56.96,31.42 56.96,53.36 56.35,53.97 53.91,53.97 53.3,54.58 53.3,58.44 53.91,59.05 56.35,59.05 61.43,64.13 68.95,64.13 71.59,66.77 71.59,69.21 70.98,69.82 52.9,69.82 44.56,61.49 16.52,61.49 14.08,59.05 12.66,59.05 10.63,57.02 7.18,57.02 LCD2.5
N$23
  Top 0.508: IC9.13 53.91,32.63 53.5,32.63 52.49,33.65 50.05,33.65 47.21,36.5 47.21,49.5 44.56,52.14 IC1.2 42.53,52.75 41.11,52.75 IC2.39 38.67,52.34 32.78,46.45 12.66,46.45 11.04,44.83 3.92,44.83 3.11,45.64 3.11,52.34 4.13,53.36 LCD2.4
N$24
  Bottom 0.508: IC9.12 53.91,34.87 52.49,34.87 IC1.12
N$25
  Bottom 0.508: IC9.11 53.91,37.51 52.49,37.51 IC1.13
N$26
  Bottom 0.508: IC9.10 53.91,39.95 52.49,39.95 IC1.14
N$27
  Top 0.508: IC9.9 53.91,42.59 52.49,42.59 IC1.15
N$28
  Top 0.508: IC9.8 53.91,45.03 52.49,45.03 IC1.16
N$29
  Top 0.508: IC9.7 53.91,47.67 52.49,47.67 IC1.17
N$30
  Top 0.508: IC9.6 53.91,50.11 52.49,50.11 IC1.18
N$31
  Top 0.508: IC9.5 53.91,52.75 52.49,52.75 IC1.19
N$32
  Top 0.508: IC9.24 61.63,43 61.63,43.61 60.82,44.42 60.82,60.88 61.43,61.49 64.07,61.49 69.36,56.21 69.36,22.88 50.86,4.39 35.83,4.39 25.87,14.35 IC2.17 23.64,15.16 22.62,16.18 22.62,16.78 21.6,17.8 IC3.2
N$33
  Bottom 0.508: IC9.29 63.66,54.78 63.66,54.17 72.81,45.03 72.81,43.81 75.45,41.17 78.5,41.17 79.11,40.56 79.11,31.01 53.3,5.2 37.66,5.2 25.87,16.99 IC2.16
N$34
  Top 0.508: IC3.3 21.81,21.46 21.81,22.07 24.04,24.3 IC2.13
N$35
  Top 0.508: IC3.1 19.57,15.57 16.32,15.57 15.51,14.75 9.21,14.75 7.18,16.78 LCD1.5
N$36
  Bottom 0.508: IC2.15 23.43,19.63 19.37,19.63 12.26,12.52 7.18,12.52 LCD1.3
N$37
  Bottom 0.508: IC2.14 23.43,22.07 19.37,22.07 14.29,16.99 9.21,16.99 7.18,14.96 LCD1.4
N$38
  Bottom 0.508: IC2.30 40.7,30.4 40.7,30.81 41.72,31.82 41.72,32.84 42.53,33.65 47.21,33.65 48.22,32.63 50.05,32.63 IC1.11
N$39
  Top 0.508: IC9.27 63.66,49.7 63.66,49.09 67.73,45.03 67.73,23.29 52.08,7.64 41.52,7.64 41.11,7.23 IC2.21
N$40
  Top 0.508: IC9.26 63.66,47.06 63.66,46.66 66.92,43.4 66.92,23.49 53.1,9.67 41.11,9.67 IC2.22
N$41
  Bottom 0.508: IC9.23 63.66,39.54 63.66,38.93 67.73,34.87 67.73,24.3 55.74,12.31 41.11,12.31 IC2.23
N$42
  Top 0.508: IC9.25 63.66,44.62 63.66,44.01 64.48,43.2 64.48,36.7 66.1,35.07 66.1,23.69 55.13,12.72 42.74,12.72 41.11,14.35 IC2.24
N$43
  Bottom 0.508: IC9.4 56.15,54.78 56.15,54.17 60.01,50.31 60.01,37.71 61.63,36.09 64.07,36.09 66.1,34.06 66.1,24.71 61.84,20.44 41.52,20.44 41.11,20.85 38.47,20.85 38.06,20.44 38.06,18.41 38.88,17.6 IC2.25
N$44
  Bottom 0.508: IC9.28 63.66,52.14 63.66,51.74 69.36,46.05 69.36,23.29 54.32,8.25 38.67,8.25 37.25,9.67 37.25,14.55 38.67,15.97 41.11,15.97 41.72,16.58 41.72,18.41 40.91,19.22 IC2.26
N$45
  Top 0.508: IC9.3 55.94,57.22 55.94,56.82 60.01,52.75 60.01,37.71 61.63,36.09 64.07,36.09 65.29,34.87 65.29,23.9 56.76,15.36 45.58,15.36 44.97,15.97 44.97,18.41 41.11,22.27 IC2.27
N$46
  Bottom 0.508: IC5.25 27.29,57.42 25.46,55.6 IC2.1
N$47
  Bottom 0.508: IC5.24 29.32,55.39 28.31,55.39 25.87,52.95 IC2.2
N$48
  Bottom 0.508: IC5.23 30.14,55.39 30.14,54.58 25.87,50.31 IC2.3
N$49
  Bottom 0.508: IC5.22 30.95,55.39 30.95,53.36 25.67,48.08 IC2.4
N$50
  Bottom 0.508: IC5.21 31.76,55.39 31.76,51.94 25.46,45.64 IC2.5
N$51
  Bottom 0.508: IC5.12 37.25,60.68 37.66,60.68 37.86,60.47 37.86,44.62 25.87,32.63 IC2.10
N$53
  Top 0.508: R8.1 36.84,72.66 32.17,67.99 R9.2
  Bottom 0.508: IC5.4 31.76,65.35 31.76,67.38 R9.2
N$54
  Top 0.508: R8.2 45.38,73.48 45.38,75.51 USB.1
N$55
  Top 0.508: R10.2 43.95,65.96 43.95,69.62 43.75,69.82 43.75,75.1 USB.2
N$56
  Top 0.508: R11.2 49.44,78.96 47,78.96 46.8,79.17 42.94,79.17 41.92,78.15 USB.3
N$57
  Top 0.508: R11.1 49.44,70.84 45.38,70.84 R12.1
  Bottom 0.508: IC5.7 34.2,65.35 34.2,65.76 35.22,66.77 35.42,66.77 36.03,67.38 36.03,68.4 36.84,69.21 43.34,69.21 44.36,70.23 R12.1
N$58
  Bottom 0.508: IC5.8 35.22,65.15 36.03,65.15 R10.1
N$59
  Bottom 0.508: IC5.5 32.58,65.35 32.58,67.18 33.59,68.19 33.59,68.6 35.01,70.02 36.84,70.02 R12.2
N$60
  Bottom 0.508: IC5.6 33.39,65.35 33.39,66.37 34.4,67.38 C4.2
N$61
  Top 0.508: R13.1 C5.2
  Bottom 0.508: IC5.30 27.29,61.49 23.84,61.49 21.4,63.93 15.91,63.93 13.88,61.9 11.24,61.9 C5.2
N$62
  Top 0.508: IC6.3 25.46,73.68 28.11,71.04 28.11,69.82 R14.1
  Bottom 0.508: IC5.2 30.14,65.35 30.14,67.18 28.71,68.6 R14.1
N$63
  Top 0.508: R15.2 11.24,77.95 22.62,77.95 23.43,77.14 IC6.4 25.87,76.93 27.9,76.93 R14.2
N$64
  Bottom 0.508: IC5.32 27.29,63.32 27.29,66.77 25.46,68.6 IC6.1
N$65
  Bottom 0.508: IC5.1 29.32,65.35 29.32,66.57 26.48,69.41 26.48,70.43 25.67,71.24 IC6.2
N$67
  Top 0.508: C6.1 14.9,66.37 16.73,66.37 20.18,62.91 Q1.1
  Bottom 0.508: IC5.28 27.29,59.86 24.04,59.86 21.4,62.5 Q1.1
N$68
  Top 0.508: C7.1 13.68,57.83 20.18,57.83 Q1.2
  Bottom 0.508: IC5.27 27.29,59.05 22.42,59.05 21.4,58.03 Q1.2
N$69
  Top 0.508: 85.61,71.85 85.61,72.46 R17.1 85.61,73.48 85.61,75.1 R18.1 85.61,76.12 85.61,77.54 R19.1 86.02,78.15 88.66,78.15 C10.+ | 85.61,71.85 85.61,71.04 R16.1 | IC7.IN 88.05,71.85 85.61,71.85
N$70
  Top 0.508: IC9.31 63.66,59.86 63.66,59.25 68.54,54.38 68.54,23.08 50.66,5.2 39.08,5.2 38.06,6.22 38.06,23.49 38.88,24.3 IC2.28
N$71
  Bottom 0.508: IC8.13 104.51,57.63 105.12,57.63 R20.2 105.12,57.02 105.12,51.94 104.3,51.12 104.3,50.72 IC8.10
N$73
  Top 0.508: C13.2 92.52,55.19 94.55,55.19 IC8.3
N$75
  Top 0.508: L1.1 105.93,16.99 105.93,37.92 D1.C 105.52,39.54 104.3,40.76 104.3,44.62 IC8.8
N$78
  Top 0.508: R21.1 88.86,23.9 87.03,23.9 85.2,25.73 R23.E
N$79
  Top 0.508: R23.A 79.52,26.94 79.52,33.45 81.34,35.28 R23.S
  Bottom 0.508: IC8.1 94.55,60.07 93.94,59.46 89.88,59.46 R22.2 89.06,58.44 89.06,57.22 82.16,50.31 82.16,37.1 R23.S
POWERJACK
  Bottom 0.508: IC5.16 35.83,57.42 35.83,43.61 25.87,33.65 23.43,33.65 22.82,33.04 22.82,31.21 23.64,30.4 IC2.11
